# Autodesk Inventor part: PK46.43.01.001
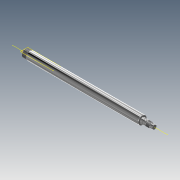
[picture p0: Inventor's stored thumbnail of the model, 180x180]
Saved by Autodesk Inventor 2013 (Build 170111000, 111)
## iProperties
Shininess: 64.0
Length Units: 11269
Angle Units: 11279
Time Units: 11290
Mass Units: 11283
Length Display Precision: 3
Angle Display Precision: 2
Compacted: True
Part Number: PK46.43.01.001
Document SubType Name: Modeling
Created: 2004-11
Material: Steel, High Strength Low Alloy
Designer: ELarisa
Manufacturer: Standard
Standards Organization: Custom
Density: 7.84 g/cm^3
Density: 0.0
Volumn: 0.0
Area: 0.0
PropertySet Name: Model Information
Control State: 0
Master: False
Checked Out: False
Checked Out Date: 2008-10-09
Last Check In Date: 2008-10-09
Author: ELarisa
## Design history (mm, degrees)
sketch "Эскиз1"
  geometry: L1 (-25.116, -3.451)-(-25.116, 26.549); L2 (-25.116, 26.549)-(-23.116, 28.549); L3 (-23.116, 28.549)-(8.384, 28.549); L4 (8.384, 28.549)-(9.884, 27.049); L5 (9.884, 27.049)-(14.884, 27.049); L6 (17.482, 31.549)-(939.884, 31.549); L7 (939.884, 31.549)-(944.884, 30.21); L8 (944.884, 30.21)-(944.884, 18.549); L9 (944.884, 18.549)-(964.884, 18.549); L10 (964.884, 18.549)-(964.884, 16.699); L11 (964.884, 16.699)-(968.484, 16.699); L12 (968.484, 16.699)-(968.484, 18.549); L13 (968.484, 18.549)-(982.884, 18.549); L14 (982.884, 18.549)-(983.884, 17.549); L15 (983.884, 17.549)-(983.884, 16.049); L16 (983.884, 16.049)-(988.884, 16.049); L17 (988.884, 16.049)-(990.384, 17.549); L18 (990.384, 17.549)-(1019.884, 17.549); L19 (1019.884, 17.549)-(1021.884, 15.549); L20 (1021.884, 15.549)-(1021.884, 14.549); L21 (1021.884, 14.549)-(1042.384, 14.549); L22 (1042.384, 14.549)-(1043.884, 13.049); L23 (1043.884, 13.049)-(1043.884, -3.451); L24 (1043.884, -3.451)-(-25.116, -3.451); L25 (17.482, 31.549)-(14.884, 27.049)
  constraints: 50 end point, 17 parallel, 1 collinear, 1 perpendicular, 1 vertical
  dimensions: "d0" = 1069 distance of L23.end L1.start; "d3" = 135 deg angle of L3 L2; "d4" = 135 deg angle of L3 L4; "d6" = 18 distance between parallel lines of L24 L21; "d8" = 60 distance from line of L23 L14.end; "d9" = 99 distance between parallel lines of L23 L8; "d10" = 15 deg angle of L7 L6; "d11" = 5 horizontal distance of L6.end L7.end; "d12" = 20 distance from line of L10.end L8; "d13" = 3.6 distance of L10.end L11.end; "d14" = 5 distance of L15.end L16.end; "d15" = 135 deg angle of L16 L17; "d16" = 135 deg angle of L19 L18; "d17" = 135 deg angle of L14 L13 (derived); "d18" = 35 distance between parallel lines of L24 L6; "d19" = 32 distance between parallel lines of L24 L3; "d20" = 30.5 distance from line of L24 L4.end; "d21" = 22 distance between parallel lines of L24 L9; "d22" = 21 distance between parallel lines of L24 L18; "d23" = 19.5 distance between parallel lines of L24 L16; "d24" = 20.15 distance between parallel lines of L24 L11; "d25" = 135 deg angle of L22 L21 (derived); "d26" = 22 distance between parallel lines of L23 L20; "d27" = 1.5 horizontal distance of L22.end L21.end; "d28" = 2 horizontal distance of L19.end L18.end; "d29" = 1 horizontal distance of L13.end L14.end; "d30" = 2 horizontal distance of L1.end L2.end; "d43" = 5 distance of L4.end L5.end; "d44" = 60 deg angle of L6 L25; "d45" = 40 distance from line of L5.end L1
revolve "Вращение1" sketch "Эскиз1" stored, may be unused: angle "d31" = 90 deg
node "РабОсь1"
node "РабПлоскость1"
sketch "Эскиз2"
  geometry: L1 (-238.916, -3.451)-(1257.684, -3.451) reference; L2 (1043.884, -19.951)-(1043.884, 13.049) reference; C1 r 4 at (1029.884, -3.451)
  constraints: 1 centre point
  dimensions: "d33" = 0 distance from line of L1 C1.centre; "d34" = 14 distance from line of L2 C1.centre; "d37" = 8 diameter of C1
extrude "Выдавливание1" cut sketch "Эскиз2" stored distance "d35" = 10; taper "d36" = 0 deg
feature "Резьба1" dims "d38" = 10, "d39" = 0
feature "Резьба2" dims "d40" = 10, "d41" = 0
body "Solid1"
other parameters: "d32" = 18
